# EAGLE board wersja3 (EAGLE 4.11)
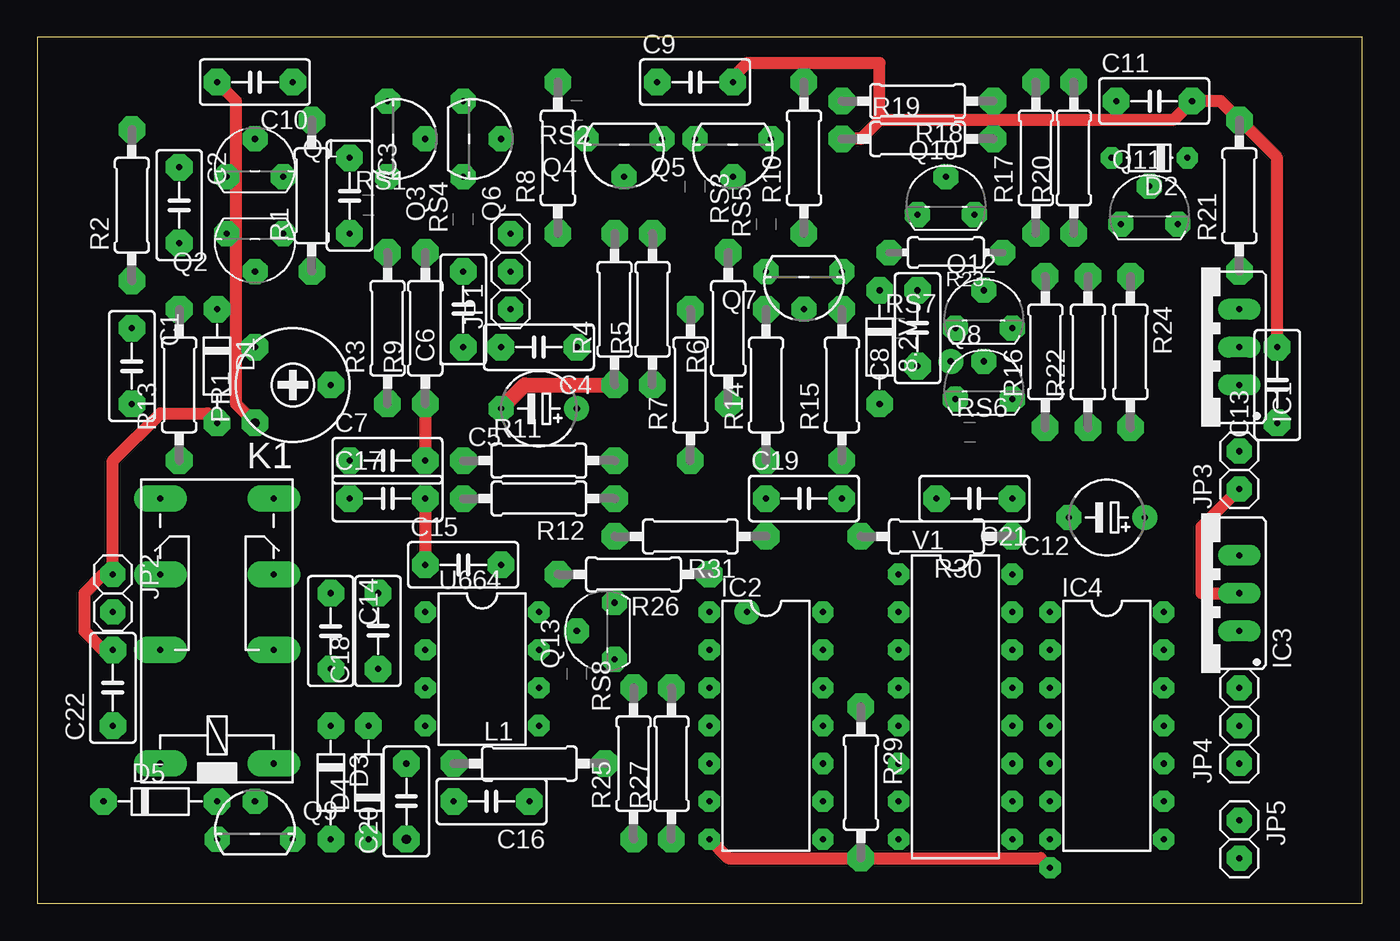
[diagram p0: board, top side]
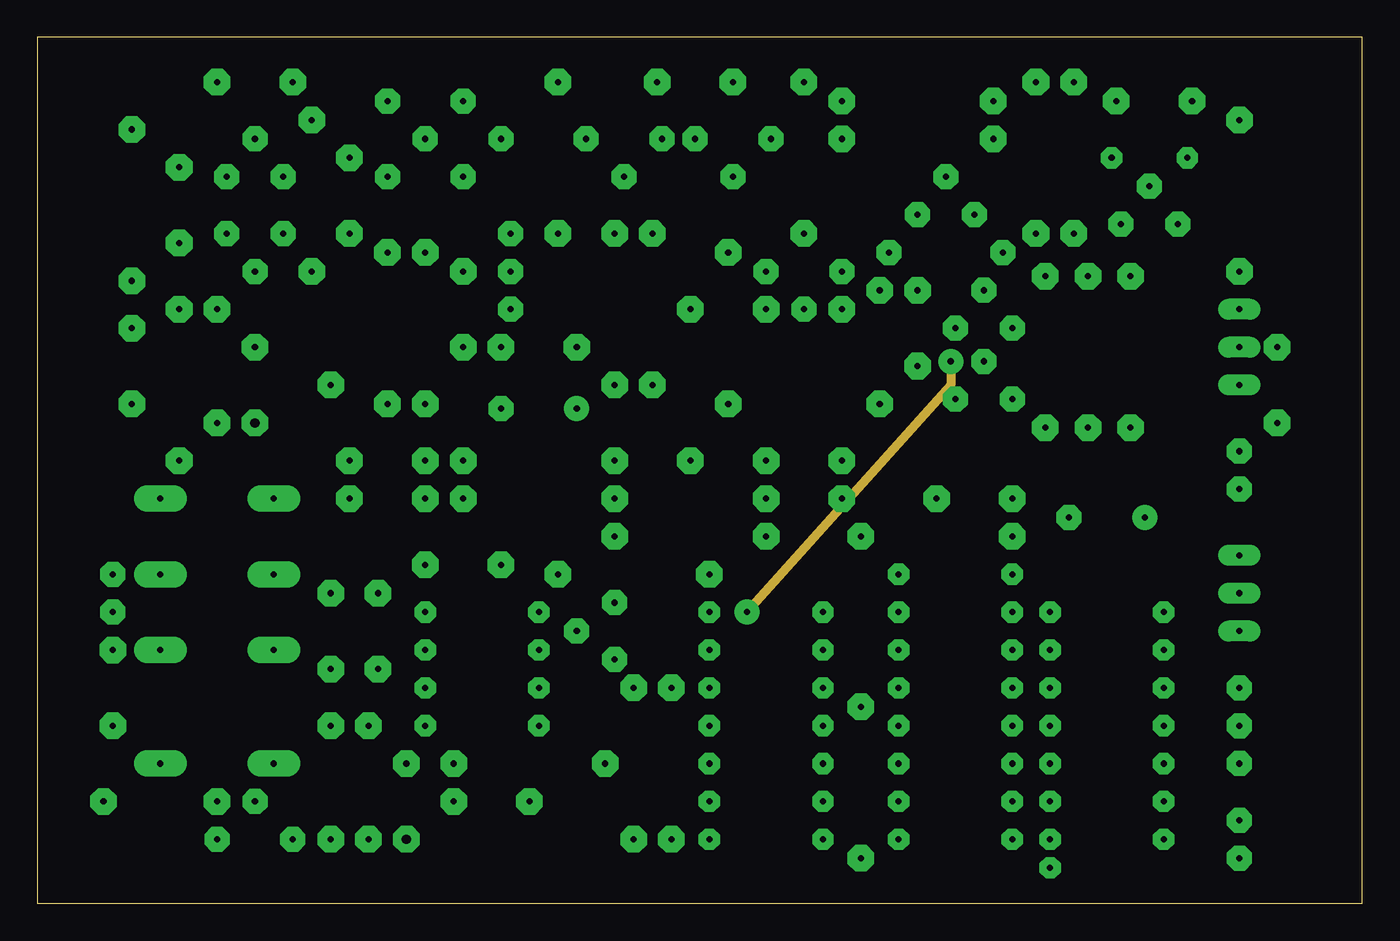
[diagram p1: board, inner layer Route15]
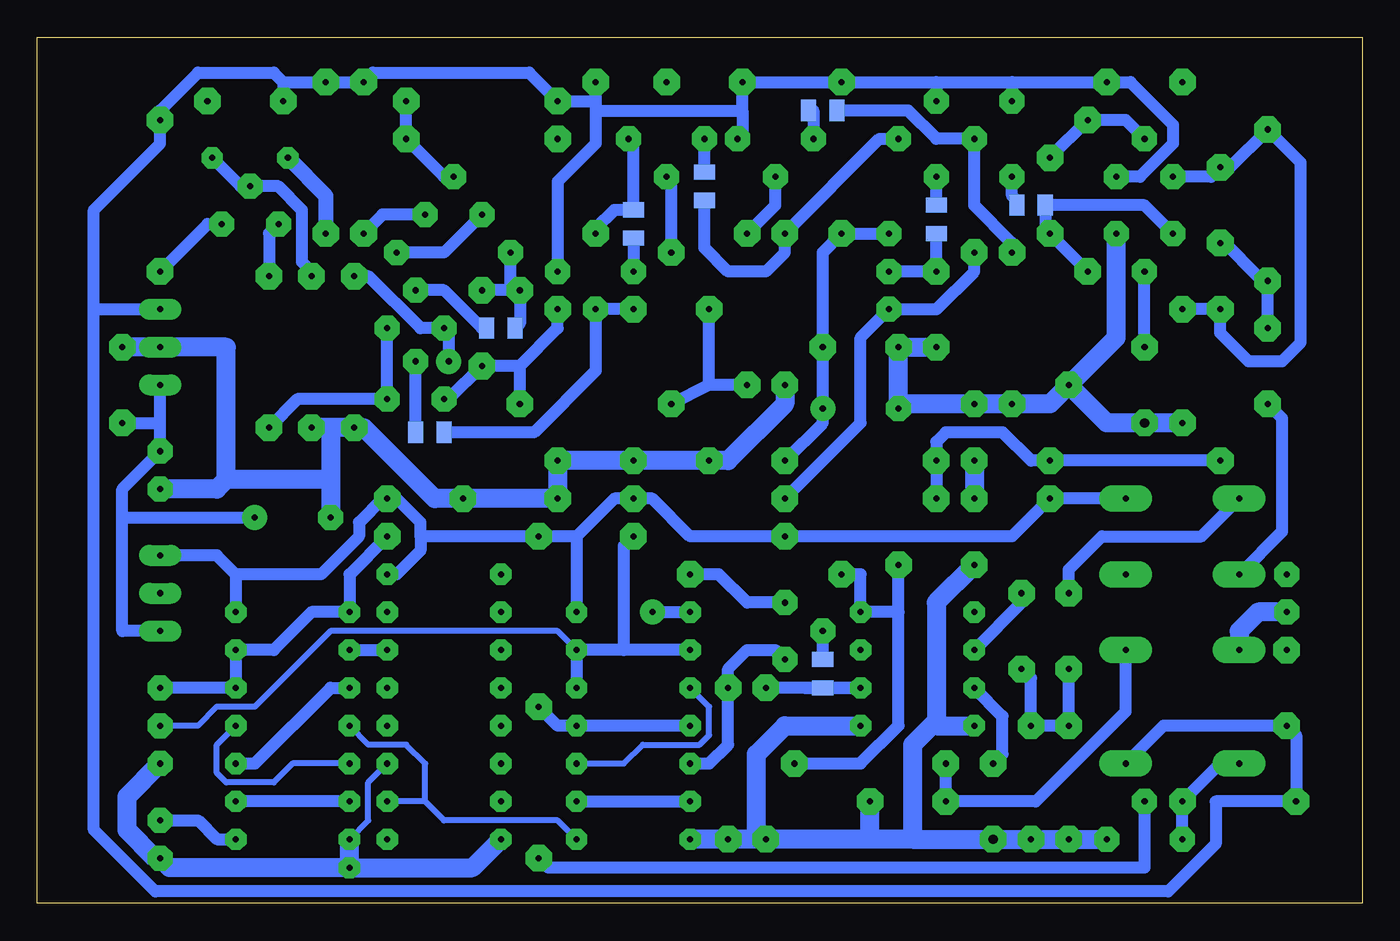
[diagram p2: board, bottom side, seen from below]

Size 88.88 x 58.09 mm. Coordinates in mm from the lower left corner, seen from the top.
Outline: 0,0 88.88,0 88.88,58.09 0,58.09 0,0
Copper layers (1*16): Top 0.035mm / dielectric 1.5mm / Bottom 0.035mm
Design rules "default": minimum track width 10mil, minimum drill 24mil, track to track 8mil, track to pad 8mil, pad to pad 8mil, via to via 8mil, smd to smd 8mil, copper to edge 8mil, drill to drill 8mil, minimum pad ring 10mil, minimum via ring 8mil, stop-mask expansion 4mil, vias tented up to drill 0mil, thermal gap 10mil

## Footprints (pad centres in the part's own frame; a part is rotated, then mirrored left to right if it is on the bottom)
D-7.5 = drill 0.406 pad 1.778 octagon: A 3.81,0; C -3.81,0
C050-030X075 = drill 0.406 pad 1.778 octagon: 1 -2.54,0; 2 2.54,0
E5-5 = drill 0.406 pad 1.676 round: + -2.54,0 | drill 0.406 pad 1.676 octagon: - 2.54,0
D-5 = drill 0.406 pad 1.422 octagon: A 2.54,0; C -2.54,0
78XXS = drill 0.406 pad 1.422 long: GND 0,-2.54; IN -2.54,-2.54; OUT 2.54,-2.54
DIL14 = drill 0.406 pad 1.422 octagon: 1 -7.62,-3.81; 2 -5.08,-3.81; 3 -2.54,-3.81; 4 0,-3.81; 5 2.54,-3.81; 6 5.08,-3.81; 7 7.62,-3.81; 8 7.62,3.81; 9 5.08,3.81; 10 2.54,3.81; 11 0,3.81; 12 -2.54,3.81; 13 -5.08,3.81; 14 -7.62,3.81
1X03 = drill 0.406 pad 1.676 octagon: 1 -2.54,0; 2 0,0; 3 2.54,0
1X02 = drill 0.406 pad 1.676 octagon: 1 -1.27,0; 2 1.27,0
351 = drill 0.406 pad 1.778 long: 1 -3.81,-3.81; 16 -3.81,3.81; O1 8.89,-3.81; O2 8.89,3.81; P1 3.81,-3.81; P2 3.81,3.81; S1 13.97,-3.81; S2 13.97,3.81
0207/10 = drill 0.406 pad 1.778 octagon: 1 -5.08,0; 2 5.08,0
RES_TRIMM = drill 0.406 pad 1.778 octagon: 1 -2.54,2.54; 2 0,-2.54; 3 2.54,2.54
TO92 = drill 0.406 pad 1.676 octagon: 1 1.905,-1.27; 2 0,1.27; 3 -1.905,-1.27
TO92' = drill 0.406 pad 1.676 octagon: 1 2.54,-1.27; 2 0,1.27; 3 -2.54,-1.27
TO92-EBC = drill 0.406 pad 1.676 octagon: B 0,0; C -1.905,-2.54; E 1.905,-2.54
0204/7 = drill 0.406 pad 1.676 octagon: 1 -3.81,0; 2 3.81,0
0805 = smd 1.016 x 1.422 bottom: P$1 -0.953,0; P$2 0.953,0
DIL08 = drill 0.406 pad 1.422 octagon: 1 -3.81,-3.81; 2 -1.27,-3.81; 3 1.27,-3.81; 4 3.81,-3.81; 5 3.81,3.81; 6 1.27,3.81; 7 -1.27,3.81; 8 -3.81,3.81
DIL16 = drill 0.406 pad 1.422 octagon: 1 -8.89,-3.81; 2 -6.35,-3.81; 3 -3.81,-3.81; 4 -1.27,-3.81; 5 1.27,-3.81; 6 3.81,-3.81; 7 6.35,-3.81; 8 8.89,-3.81; 9 8.89,3.81; 10 6.35,3.81; 11 3.81,3.81; 12 1.27,3.81; 13 -1.27,3.81; 14 -3.81,3.81; 15 -6.35,3.81; 16 -8.89,3.81

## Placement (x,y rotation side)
8.2V  DZ1  [D-7.5]  56.51,37.3 270 top
C1  47nF  [C050-030X075]  6.34,36.03 270 top
C2  47p  [C050-030X075]  9.52,46.82 270 top
C3  47p  [C050-030X075]  20.95,47.46 270 top
C4  22n  [C050-030X075]  33.65,37.3 180 top
C5  10u  [E5-5]  33.65,33.17 180 top
C6  100n  [C050-030X075]  28.57,39.84 90 top
C7  22n  [C050-030X075]  23.49,29.68 0 top
C8  1n  [C050-030X075]  59.05,38.57 90 top
C9  22n  [C050-030X075]  44.13,55.08 0 top
C10  22n  [C050-030X075]  14.6,55.08 180 top
C11  22n  [C050-030X075]  74.92,53.81 0 top
C12  100u  [E5-5]  71.75,25.87 180 top
C13  22n  [C050-030X075]  83.18,34.76 90 top
C14  1n  [C050-030X075]  19.68,18.25 270 top
C15  22n  [C050-030X075]  28.57,22.7 0 top
C16  22n  [C050-030X075]  30.47,6.82 180 top
C17  22n  [C050-030X075]  23.49,27.14 0 top
C18  1n  [C050-030X075]  22.86,18.25 90 top
C19  22n  [C050-030X075]  51.43,27.14 0 top
C20  1n  [C050-030X075]  24.76,6.82 90 top
C21  22n  [C050-030X075]  62.86,27.14 180 top
C22  22n  [C050-030X075]  5.08,14.44 90 top
D1  bat42  [D-7.5]  12.06,36.03 270 top
D2  [D-5]  74.61,50 180 top
D3  bat42  [D-7.5]  19.68,8.09 270 top
D4  bat42  [D-7.5]  22.22,8.09 90 top
D5  1n4148  [D-7.5]  8.25,6.82 0 top
IC1  uA7812  [78XXS]  78.1,37.3 90 top
IC2  74ACT00N  [DIL14]  48.89,11.9 270 top
IC3  [78XXS]  78.1,20.79 90 top
IC4  74ACT00N  [DIL14]  71.75,11.9 270 top
JP1  [1X03]  31.75,42.38 90 top
JP2  [1X02]  5.08,20.79 270 top
JP3  [1X02]  80.64,29.05 90 top
JP4  [1X03]  80.64,11.9 90 top
JP5  [1X02]  80.64,4.28 270 top
K1  351  [351]  12.06,13.17 90 top
L1  [0207/10]  33.02,9.36 0 top
PR1  470  [RES_TRIMM]  17.14,34.76 90 top
Q1  BF245  [TO92]  14.6,50 0 top
Q2  BF245  [TO92]  14.6,43.65 180 top
Q3  BF199  [TO92']  24.76,51.27 270 top
Q4  BFR91  [TO92']  39.36,50 180 top
Q5  BFR91  [TO92']  46.67,50 180 top
Q6  BF240  [TO92']  29.84,51.27 270 top
Q7  BF240  [TO92']  51.43,41.11 180 top
Q8  BF414  [TO92-EBC]  63.49,36.35 0 top
Q9  BC547  [TO92']  14.6,5.55 0 top
Q10  BF414  [TO92-EBC]  60.95,48.73 0 top
Q11  BF414  [TO92-EBC]  74.61,48.09 0 top
Q12  BF414  [TO92-EBC]  63.49,41.11 0 top
Q13  BF414  [TO92-EBC]  36.19,18.25 90 top
R1  150  [0207/10]  18.41,47.46 90 top
R2  1k  [0207/10]  6.34,46.82 90 top
R3  1k  [0207/10]  23.49,38.57 90 top
R4  [0207/10]  38.73,39.84 90 top
R5  2.2  [0207/10]  41.27,39.84 90 top
R6  2.2  [0207/10]  46.35,38.57 90 top
R7  330  [0207/10]  43.81,34.76 90 top
R8  3.3k  [0207/10]  34.92,50 90 top
R9  3.3k  [0207/10]  26.03,38.57 90 top
R10  330  [0207/10]  51.43,50 90 top
R11  1k  [0207/10]  33.65,29.68 0 top
R12  1k  [0207/10]  33.65,27.14 180 top
R13  1M  [0207/10]  9.52,34.76 90 top
R14  1k  [0207/10]  48.89,34.76 90 top
R15  68  [0207/10]  53.97,34.76 90 top
R16  220  [0207/10]  67.62,36.98 90 top
R17  100  [0207/10]  66.99,50 90 top
R18  330  [0207/10]  59.05,53.81 180 top
R19  2.2k  [0207/10]  59.05,51.27 0 top
R20  240  [0207/10]  69.53,50 90 top
R21  68  [0207/10]  80.64,47.46 90 top
R22  2.2k  [0207/10]  70.48,36.98 90 top
R23  100  [0204/7]  60.95,43.65 180 top
R24  33  [0207/10]  73.34,36.98 270 top
R25  3.3k  [0207/10]  40,9.36 90 top
R26  100  [0207/10]  40,22.06 180 top
R27  1k  [0207/10]  42.54,9.36 90 top
R29  3.3k  [0207/10]  55.24,8.09 270 top
R30  22k  [0207/10]  60.32,24.6 180 top
R31  22k  [0207/10]  43.81,24.6 180 top
RS1  22  [0805]  22.22,46.82 0 top
RS2  22  [0805]  36.19,53.17 180 top
RS3  22  [0805]  44.13,48.09 270 top
RS4  22  [0805]  28.57,45.87 90 top
RS5  22  [0805]  48.89,45.55 90 top
RS6  22  [0805]  62.54,31.59 0 top
RS7  22  [0805]  57.78,38.57 0 top
RS8  22  [0805]  36.19,15.39 270 top
U664  [DIL08]  29.84,15.71 270 top
V1  744040N  [DIL16]  61.59,13.17 270 top

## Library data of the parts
8.2V D1-D5 = diode
C1-C22 L1 R1-R27 R29-R31 = rcl
IC1 IC3 = v-reg
IC2 IC4 = 74xx-eu
JP1-JP5 = pinhead
K1 = relay
PR1 RS1-RS8 = fimek
Q1 Q2 = transistor-fet
Q3-Q7 Q9 = transistor-npn
Q8 Q10-Q13 = transistor-pnp
U664 = ic-package
V1 = 74ttl-din

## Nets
GND: C4.2 C5.- C6.1 C7.2 C9.2 C10.2 C11.2 C12.- C13.2 C15.1 C16.1 C17.2 C19.2 C20.1 C21.2 C22.2 D1.A D3.A D4.C IC1.GND IC2.7 IC3.GND IC4.7 JP2.1 JP3.1 JP4.1 JP5.2 PR1.1 PR1.2 Q2.3 Q9.1 R3.1 R4.1 R7.1 R9.1 R14.1 R15.1 R16.1 R19.1 R22.1 R25.1 R27.1 U664.4 U664.5 V1.8 V1.11
N$1: PR1.3 Q2.2
N$2: C9.1 C10.1 C11.1 C22.1 D5.C IC1.OUT K1.1 Q1.1 Q3.3 Q4.3 Q6.3 Q7.3 R8.2 R10.2 R17.2 R18.2 R20.2 R21.2
N$3: C3.2 Q2.1 R1.1 RS1.P$1
N$4: Q3.2 R3.2 RS2.P$2
N$5: C3.1 Q1.2 R1.2
N$6: C2.1 D1.C Q1.3 R2.2 R13.2
N$7: C1.1 C2.2 R2.1
N$8: C6.2 JP1.2 RS4.P$1
N$9: Q4.1 RS2.P$1
N$10: Q5.1 RS3.P$1
N$11: Q6.2 R4.2 RS3.P$2
N$12: Q4.2 R5.2
N$13: Q5.2 R6.2
N$14: R5.1 R6.1 R7.2
N$15: Q3.1 RS1.P$2
N$16: Q6.1 RS4.P$2
N$17: JP1.1 R9.2 R12.1
N$18: C4.1 C5.+ JP1.3 R8.1 R11.2
N$19: Q5.3 R10.1 RS5.P$2
N$20: C7.1 R11.1 R12.2 R13.1
N$21: C1.2 K1.O2
N$22: Q7.1 RS5.P$1
N$23: Q7.2 R14.2 RS6.P$1
N$24: Q10.E R17.1
N$25: IC2.1 Q12.C R16.2
N$26: Q8.E Q12.E R24.2
N$27: 8.2V.A C8.1 Q8.C R15.2
N$28: 8.2V.C C8.2 R23.2 RS7.P$1
N$29: Q11.E R21.1
N$30: D2.C Q11.B R22.2
N$31: Q10.B R18.1 R19.2
N$32: D2.A R20.1
N$33: C12.+ C13.1 IC1.IN IC3.IN JP3.2
N$34: Q10.C R23.1
N$35: Q11.C R24.1
N$36: Q8.B RS6.P$2
N$37: Q12.B RS7.P$2
N$38: C16.2 K1.P1 L1.1
N$39: IC2.4 IC2.11 R29.1
N$40: IC2.2 IC2.12 IC2.13 JP4.2 R31.1
N$41: IC2.3 IC2.10
N$42: IC2.6 IC2.9
N$43: JP2.2 K1.P2
N$44: C14.1 K1.S2
N$45: C17.1 C19.1 C21.1 IC2.14 IC3.OUT IC4.14 K1.S1 R30.2 R31.2 V1.16
N$46: D5.A K1.16 Q9.3
N$47: IC2.8 IC4.4 V1.10
N$48: C15.2 L1.2 R26.2 U664.8
N$49: Q9.2 R29.2
N$50: Q13.E R26.1
N$51: IC4.5 IC4.11
N$52: IC4.1 IC4.12 IC4.13 JP4.3 R30.1
N$53: Q13.B RS8.P$1
N$54: IC4.2 V1.14
N$55: C14.2 C18.1 D3.C D4.A
N$56: IC4.3 IC4.10
N$57: IC2.5 Q13.C R27.2
N$58: R25.2 RS8.P$2 U664.6
N$59: IC4.6 IC4.9
N$60: IC4.8 JP5.1
N$73: C18.2 U664.2
N$76: C20.2 U664.3

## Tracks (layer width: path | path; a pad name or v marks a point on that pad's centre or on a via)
GND  (via drill 0.41 pad 1.42, 0.61)
  Top 0.813: PR1.1 13.33,33.49 13.33,53.81 C10.2 | C9.2 46.67,55.4 47.62,56.35 56.51,56.35 56.51,52.54 | 56.51,52.54 55.24,51.27 R19.1 | D1.A 11.43,32.85 8.25,32.85 5.08,29.68 JP2.1 4.44,22.06 3.17,20.79 3.17,18.25 4.44,16.98 C22.2 | R9.1 C7.2 | C17.2 C15.1 | IC2.7 46.35,3.01 67.3,3.01 v67.94,2.38 | IC3.GND 78.1,20.79 78.1,25.23 JP3.1 | C13.2 83.18,50 79.37,53.81 C11.2 76.19,52.54 56.51,52.54
  Top 1.016: R4.1 32.7,34.76 C5.-
  Bottom 0.406: V1.11 66.67,8.09 66.67,5.55 IC4.7
  Bottom 1.016: 31.11,33.49 C5.- | 67.3,31.9 R16.1 | 28.57,12.22 28.73,12.06 | 28.73,12.06 28.57,11.9 | 28.73,12.06
  Bottom 1.27: PR1.2 17.14,32.22 PR1.1 D1.A | Q2.3 16.5,37.93 PR1.2 | PR1.2 20.95,33.49 R3.1 R9.1 31.11,33.49 C4.2 C6.1 | 30.16,4.28 C20.1 D4.C D3.A Q9.1 | 30.16,4.28 33.02,4.28 | 33.02,4.28 R25.1 | 33.02,4.28 C16.1 | v67.94,2.38 80,2.38 JP5.2 80.96,3.01 82.86,4.92 82.86,7.14 JP4.1 | C7.2 C17.2 | v67.94,2.38 IC4.7 | R25.1 R27.1 IC2.7 | V1.8 59.69,2.38 v67.94,2.38 | R4.1 38.73,33.49 42.54,29.68 R7.1 R14.1 R15.1 C19.2 C21.2 62.22,27.14 66.99,31.9 67.3,31.9 | 69.21,31.9 69.21,28.41 | 69.21,28.41 C12.- | R16.1 69.21,31.9 | 69.21,31.9 R22.1 | 69.21,28.41 76.19,28.41 | 76.19,28.41 76.83,27.78 JP3.1 | 76.19,28.41 76.19,37.3 IC1.GND C13.2 | C15.1 28.57,20.16 28.57,12.22 | 28.73,12.06 30.16,10.63 30.16,4.28 | 28.57,11.9 U664.4 | U664.5 38.73,11.9 40.63,10 40.63,4.28 R25.1
  other vias: 24.76,4.28 14.6,32.22
N$1
  Bottom 0.813: PR1.3 Q2.2
N$2
  Bottom 0.813: Q1.1 14.92,48.73 12.7,50.95 12.7,52.22 15.55,55.08 C10.1 23.49,55.08 | 41.59,53.17 C9.1 R8.2 28.57,55.08 | 41.59,53.17 41.59,51.59 Q4.3 | 23.49,55.08 Q3.3 | 28.57,55.08 23.49,55.08 | 28.57,55.08 Q6.3 | Q7.3 53.97,48.41 51.43,50.95 51.43,53.17 | 51.43,53.81 R10.2 51.43,53.17 | 51.43,53.81 51.43,53.17 | 51.43,53.81 R18.2 55.88,55.71 66.35,55.71 R17.2 R20.2 72.38,55.08 | 85.08,39.84 85.08,4.92 80.96,0.79 13.01,0.79 9.84,3.96 9.84,6.82 D5.C 4.44,11.27 C22.1 13.33,11.9 K1.1 | 85.08,39.84 IC1.OUT | 85.08,39.84 85.08,46.51 80.64,50.95 R21.2 80.64,53.17 78.1,55.71 73.02,55.71 72.38,55.08 | 72.38,55.08 C11.1 | 51.43,53.17 41.59,53.17
N$3
  Bottom 0.813: Q2.1 14.6,46.82 RS1.P$1 21.27,45.24 C3.2 R1.1
N$4
  Bottom 0.813: R3.2 23.49,44.28 26.03,46.82 Q3.2 28.57,51.27 30.47,53.17 RS2.P$2
N$5
  Bottom 0.813: C3.1 R1.2 15.87,52.54 Q1.2
N$6
  Bottom 0.813: D1.C R13.2 9.52,38.25 7.61,36.35 5.39,36.35 4.12,37.62 4.12,49.68 R2.2 8.89,49.36 C2.1 10.16,48.73 Q1.3
N$7
  Bottom 0.813: C2.2 9.52,44.6 6.66,41.74 R2.1 C1.1
N$8
  Bottom 0.813: RS4.P$1 C6.2 JP1.2
N$9
  Bottom 0.813: RS2.P$1 36.82,53.17 Q4.1
N$10
  Bottom 0.813: RS3.P$1 Q5.1
N$11
  Bottom 0.813: Q6.2 32.38,51.27 R4.2 38.73,43.65 40,42.38 42.54,42.38 44.13,43.97 RS3.P$2
N$12
  Bottom 0.813: Q4.2 39.36,46.82 R5.2
N$13
  Bottom 0.813: R6.2 46.35,48.09 46.67,48.41 Q5.2
N$14
  Bottom 0.813: R5.1 43.81,34.76 | 43.81,34.76 R6.1 | 43.81,34.76 R7.2
N$15
  Bottom 0.813: RS1.P$2 23.17,47.14 23.49,47.46 Q3.1
N$16
  Bottom 0.813: RS4.P$2 Q6.1
N$17
  Bottom 0.813: R9.2 26.03,42.38 28.57,39.84 JP1.1 33.65,37.93 33.65,32.22 R12.1
N$18
  Bottom 0.813: JP1.3 R8.1 36.19,43.65 C4.1 C5.+ 36.19,32.22 R11.2
N$19
  Bottom 0.813: Q5.3 48.89,50.95 RS5.P$2 50.16,46.51 51.43,45.24 R10.1
N$20
  Bottom 0.813: R13.1 C7.1 22.22,29.68 24.12,31.59 27.93,31.59 28.57,30.95 R11.1 R12.2
N$21
  Bottom 0.813: C1.2 5.39,32.54 5.39,24.92 K1.O2
N$22
  Bottom 0.813: RS5.P$1 Q7.1
N$23
  Bottom 0.813: R14.2 Q7.2 51.43,35.71 55.56,31.59 RS6.P$1
N$24
  Bottom 0.813: Q10.E 65.72,46.19 R17.1
N$25  (via drill 0.41 pad 1.68)
  Route15 0.61: v61.27,36.35 61.27,34.76 v47.62,19.52
  Bottom 0.813: R16.2 66.67,42.06 63.18,38.57 Q12.C 61.27,38.25 v61.27,36.35 | v47.62,19.52 IC2.1
N$26
  Bottom 0.813: Q12.E Q8.E 71.43,33.81 R24.2
N$27
  Bottom 0.813: R15.2 53.97,38.57 56.51,36.03 | 56.51,36.03 C8.1 61.27,33.81 Q8.C | 8.2V.A 56.51,36.03
N$28
  Bottom 0.813: 8.2V.C C8.2 | R23.2 57.14,41.11 8.2V.C | 8.2V.C 56.51,38.89 RS7.P$1
N$29
  Bottom 0.813: R21.1 77.47,45.55 Q11.E
N$30
  Bottom 0.813: D2.C 75.24,48.09 Q11.B 72.7,48.09 71.11,46.51 71.11,43.02 70.48,42.38 R22.2
N$31
  Bottom 0.813: Q10.B 61.59,48.73 R19.2 R18.1
N$32
  Bottom 1.016: D2.A 69.53,47.46 R20.1
N$33
  Bottom 0.813: 83.18,25.87 83.18,18.25 IC3.IN | 83.18,25.87 C12.+ | 83.18,25.87 83.18,27.78 JP3.2 80.64,32.22 | 80.64,32.22 IC1.IN | C13.1 80.64,32.22
N$34
  Bottom 0.813: Q10.C 61.59,43.65 R23.1
N$35
  Bottom 0.813: Q11.C 73.34,44.92 R24.1
N$36
  Bottom 0.813: RS6.P$2 Q8.B
N$37
  Bottom 0.813: RS7.P$2 59.05,38.57 61.59,41.11 Q12.B
N$38
  Bottom 0.813: K1.P1 15.87,12.85 21.9,6.82 C16.2 L1.1
N$39
  Bottom 0.813: IC2.4 IC2.11 53.97,11.9 R29.1
N$40
  Bottom 0.406: JP4.2 78.1,11.9 76.83,13.17 74.29,13.17 69.21,18.25 53.97,18.25 IC2.13
  Bottom 0.813: 49.52,16.98 IC2.13 IC2.12 | IC2.2 49.52,16.98 | 49.52,16.98 49.52,23.96 R31.1
N$41
  Bottom 0.406: IC2.10 49.52,9.36 48.25,10.63 44.45,10.63 43.81,11.27 43.81,13.17 IC2.3
N$42
  Bottom 0.813: IC2.9 IC2.6
N$43
  Bottom 1.27: JP2.2 6.98,19.52 8.25,18.25 K1.P2
N$44
  Bottom 0.813: C14.1 19.68,22.38 17.46,24.6 10.79,24.6 K1.S2
N$45
  Bottom 0.813: IC3.OUT 76.83,23.33 75.56,22.06 | 63.18,24.6 R30.2 52.7,24.6 | 75.56,22.06 IC4.14 | V1.16 64.77,22.06 63.18,23.65 63.18,24.6 | 75.56,22.06 69.84,22.06 67.3,24.6 67.3,25.55 65.72,27.14 C21.1 64.77,27.14 63.18,25.55 63.18,24.6 | 52.7,24.6 IC2.14 | K1.S1 C17.1 23.49,24.6 R31.2 45.08,24.6 47.62,27.14 C19.1 50.16,27.14 52.7,24.6
N$46
  Bottom 0.813: Q9.3 D5.A 9.52,9.36 K1.16
N$47
  Bottom 0.406: IC2.8 53.97,5.55 61.59,5.55 62.86,6.82 | 62.86,6.82 V1.10 | IC4.4 66.67,10.63 64.13,10.63 62.86,9.36 62.86,6.82
N$48
  Bottom 0.813: 31.11,19.52 U664.8 33.65,22.06 R26.2 | 31.11,19.52 C15.2 | 31.11,19.52 31.11,11.9 33.65,9.36 L1.2
N$49
  Bottom 0.813: R29.2 54.6,2.38 14.6,2.38 Q9.2
N$50
  Bottom 0.813: Q13.E 41.27,20.16 43.17,22.06 R26.1
N$51
  Bottom 0.406: IC4.5 71.75,9.36 73.02,8.09 76.19,8.09 76.83,8.72 76.83,10.63 IC4.11
N$52
  Bottom 0.813: JP4.3 IC4.12 IC4.13 73.02,16.98 70.48,19.52 IC4.1 67.94,22.06 R30.1
N$53
  Bottom 0.813: RS8.P$1 Q13.B
N$54
  Bottom 0.813: IC4.2 V1.14
N$55
  Bottom 0.813: C14.2 D3.C D4.A 22.22,15.07 C18.1
N$56
  Bottom 0.813: IC4.10 74.29,9.36 69.21,14.44 IC4.3
N$57
  Bottom 0.813: IC2.5 43.81,9.36 42.54,10.63 R27.2 42.54,15.71 41.27,16.98 39.36,16.98 Q13.C
N$58
  Bottom 0.813: 37.46,14.44 R25.2 | 37.46,14.44 RS8.P$2 U664.6 37.46,14.44
N$59
  Bottom 0.813: IC4.6 IC4.9
N$60
  Bottom 0.813: JP5.1 78.1,5.55 76.83,4.28 IC4.8
N$73
  Bottom 0.813: C18.2 22.86,20.16 U664.2
N$76
  Bottom 0.813: C20.2 24.12,10 24.12,12.54 U664.3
